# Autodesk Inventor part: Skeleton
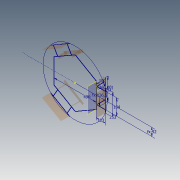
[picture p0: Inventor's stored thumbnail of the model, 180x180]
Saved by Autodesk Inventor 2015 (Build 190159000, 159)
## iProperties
Created: 2015-05
Part Number: Skeleton
Material: Generic
Document SubType Name: Modeling
Designer: TREINA6
Density: 1 g/cm^3
Appearance: Default
Author: TREINA6
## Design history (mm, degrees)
sketch "Sketch1"
  geometry: L1 (245, 141.451)-(245, -141.451); L2 (245, -141.451)-(0, -282.902); L3 (0, -282.902)-(-245, -141.451); L4 (-245, -141.451)-(-245, 141.451); L5 (-245, 141.451)-(0, 282.902); L6 (0, 282.902)-(245, 141.451); L7 (-245, 92)-(-348, 92); L8 (-348, 92)-(-348, -92); L9 (-348, -92)-(-245, -92); L10 (-245, -92)-(-245, 92); L11 (0, 0)-(610.268, 0); L12 (-348, 92)-(-348, 126.5); L13 (-348, -92)-(-348, -126.5); L14 (-348, 126.5)-(-348, -126.5); L15 (-348, -92)-(-245, -92); L16 (-348, 92)-(-245, 92); L17 (94.326, -347.377)-(64.448, -364.627); L18 (64.448, -364.627)-(283.552, -238.127); L19 (42.826, -258.176)-(94.326, -347.377); L20 (94.326, -347.377)-(253.674, -255.377); L21 (94.326, -347.377)-(42.826, -258.176); L22 (253.674, -255.377)-(283.552, -238.127); L23 (253.674, -255.377)-(202.174, -166.176); L24 (253.674, -255.377)-(202.174, -166.176); L25 (253.674, 255.377)-(283.552, 238.127); L26 (283.552, 238.127)-(64.448, 364.627); L27 (202.174, 166.176)-(253.674, 255.377); L28 (253.674, 255.377)-(94.326, 347.377); L29 (253.674, 255.377)-(202.174, 166.176); L30 (94.326, 347.377)-(64.448, 364.627); L31 (94.326, 347.377)-(42.826, 258.176); L32 (94.326, 347.377)-(42.826, 258.176); 1 further point
  constraints: 64 end point, 4 equal length, 4 vertical, 2 horizontal, 1 coincident, 1 collinear, 1 perpendicular, 1 point on line, 56 other
  dimensions: "d0" = 490 distance between parallel lines of L4 L1; "d1" = 103 distance of L9.end L8.end; "d2" = 184 distance of L8.end L7.end; "d3" = 92 distance between parallel lines of L11 L9 (= 0.5 x d2); "d4" = 253 distance of L13.end L12.end; "d7" = 360 deg dimension on point (0, 0) L12.end (derived)
extrude_surface "ExtrusionSrf1" sketch "Sketch1" dims "d9" = 100, "d10" = 0
pattern_circular "Circular Pattern1" dims angle "d12" = 360 deg
workplane "Work Plane1"
sketch "Sketch2"
  geometry: L1 (34.5, 0)-(34.5, 100); L2 (218.5, 0)-(218.5, 100); L3 (253, 100)-(0, 100); L4 (126.5, 0)-(126.5, 34.852); 4 further points
  constraints: 8 end point, 3 vertical, 1 horizontal, 1 parallel, 1 point on line
  dimensions: "d15" = 253 distance of L3.start L3.end; "d16" = 126.5 distance from line of L4 L3.end (= 0.5 x d15); "d17" = 100 distance of L2.start L2.end
extrude_surface "ExtrusionSrf4" dims "d18" = 30, "d19" = 0
extrude_surface "ExtrusionSrf5" dims "d20" = 30, "d21" = 0
extrude_surface "ExtrusionSrf6" dims "d22" = 30, "d23" = 0
pattern_circular "Circular Pattern2" dims "d25" = 360 deg
body "Srf1"
body "Srf2"
body "Srf3"
body "Srf4"
body "Srf5"
body "Srf6"
body "Srf7"
body "Srf10"
body "Srf8"
body "Srf11"
body "Srf9"
body "Srf12"
extrude_surface "ExtrusionSrf2"
extrude_surface "ExtrusionSrf3"
extrude_surface "ExtrusionSrf7"
extrude_surface "ExtrusionSrf8"
extrude_surface "ExtrusionSrf9"
extrude_surface "ExtrusionSrf10"
extrude_surface "ExtrusionSrf11"
extrude_surface "ExtrusionSrf12"
